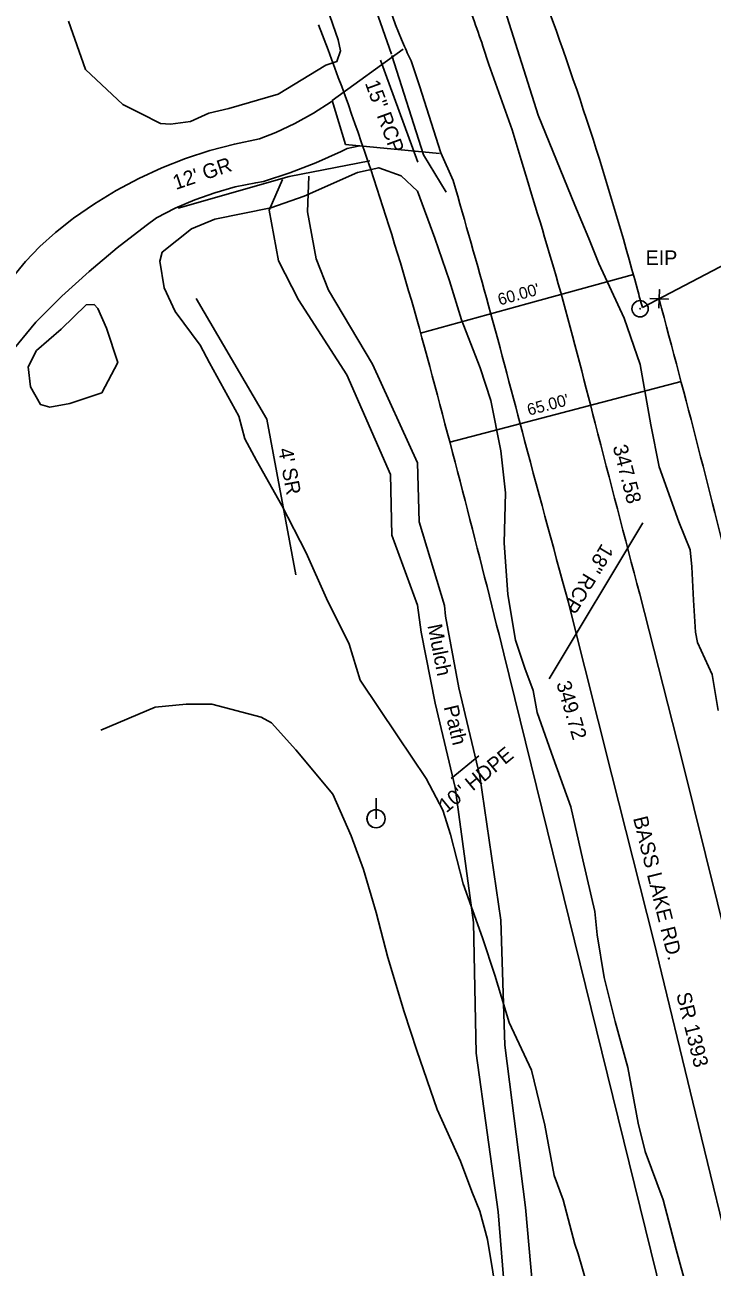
# Model space of a CAD drawing. Extents: x 2057786 to 2059508, y 687766 to 689280.
# Drawn here: x 2058906.4 to 2059093.3, y 688139 to 688476.7 of the extents above; entities that cross this region are included whole.
import ezdxf

# ---------------------------------------------------------------- set-up
doc = ezdxf.new("R2010")
doc.units = 0
for name, color, linetype in [('Exist Other Culture Fence Line', 7, 'Continuous'), ('Exist Other Culture Fence Line Text', 7, 'Continuous'), ('Exist Property Corner CELL', 7, 'Continuous'), ('Exist Property Iron Pin CELL', 7, 'Continuous'), ('Exist Property Iron Pin Text', 7, 'Continuous'), ('Exist Property Line', 7, 'Continuous'), ('Exist Right of Way Line', 7, 'Continuous'), ('Exist Right of Way Width CELL', 7, 'Continuous'), ('Exist Roads EOP', 7, 'Continuous'), ('Exist Roads EOP Other', 7, 'Continuous'), ('Exist Roads EOP Other Text', 7, 'Continuous'), ('Exist Roads EOP Text', 7, 'Continuous'), ('Exist Roads Soil', 7, 'Continuous'), ('Exist Roads Soil Text', 7, 'Continuous'), ('Exist Structure Minor Pipes HDPE 10 Inch', 7, 'Continuous'), ('Exist Structure Minor Pipes HDPE 10 Inch Text', 7, 'Continuous'), ('Exist Structure Minor Pipes RCP 15 Inch', 7, 'Continuous'), ('Exist Structure Minor Pipes RCP 15 Inch Text', 7, 'Continuous'), ('Exist Structure Minor Pipes RCP 18 Inch', 7, 'Continuous'), ('Exist Structure Minor Pipes RCP 18 Inch Invert', 7, 'Continuous'), ('Exist Structure Minor Pipes RCP 18 Inch Text', 7, 'Continuous'), ('Exist Utilities Other Pole CELL', 7, 'Continuous'), ('Exist Utilities Power Pole CELL', 7, 'Continuous'), ('Exist Utilities Telephone UG FO', 7, 'Continuous'), ('Old_Level_11', 7, 'Continuous')]:
    doc.layers.add(name, color=color, linetype=linetype)

# ---------------------------------------------------------------- blocks, each defined once
blk = doc.blocks.new('EXIST PROPERTY IRON PIN')
at = {"layer": 'Exist Property Iron Pin CELL'}
for radius in [0.0441, 0.00141]:
    blk.add_circle((0, 0), radius, dxfattribs=at)
blk = doc.blocks.new('EXIST UTILITIES OTHER POLE')
at = {"layer": 'Exist Utilities Other Pole CELL'}
blk.add_circle((0, 0), 0.0493, dxfattribs=at)

msp = doc.modelspace()

# ---------------------------------------------------------------- linework, layer by layer
at = {"layer": 'Exist Other Culture Fence Line'}
msp.add_lwpolyline([(2058980.05, 688327.2), (2058972.2, 688369.55), (2058953, 688402.37)], dxfattribs=at)
at = {"layer": 'Exist Property Corner CELL'}
msp.add_line((2059078.83, 688402.25), (2059078.83, 688402.25), dxfattribs=at)
msp.add_lwpolyline([(2059076.33, 688402.33), (2059081.32, 688402.17), (2059078.83, 688402.25), (2059078.91, 688404.75), (2059078.74, 688399.75)], dxfattribs=at)
at = {"layer": 'Exist Property Line'}
msp.add_line((2059074.29, 688399.87), (2059264.75, 688499.48), dxfattribs=at)
at = {"layer": 'Exist Right of Way Line'}
for p, q in [((2058988.82, 688469.91), (2058986.23, 688476.73)), ((2059115.34, 687986.62), (2059036.61, 688305.74))]:
    msp.add_line(p, q, dxfattribs=at)
for centre, radius, start, end in [((2058184.94, 688164.34), 920, 15.14804, 20.81311), ((2058184.94, 688164.34), 860, 15.14804, 20.81311), ((2055323.62, 687389.72), 3884.32, 15.07359, 15.14804), ((2055323.62, 687389.72), 3889.32, 13.85856, 15.08996), ((2055323.62, 687389.72), 3824.32, 13.85856, 15.14804)]:
    msp.add_arc(centre, radius, start, end, dxfattribs=at)
at = {"layer": 'Exist Right of Way Width CELL'}
for p, q in [((2059071.84, 688408.87), (2059042.87, 688400.88)), ((2059014, 688392.92), (2059042.87, 688400.88)), ((2059084.81, 688379.79), (2059050.7, 688370.81)), ((2059021.95, 688363.24), (2059050.7, 688370.81))]:
    msp.add_line(p, q, dxfattribs=at)
at = {"layer": 'Exist Roads EOP'}
for p, q in [((2059030.96, 688470.96), (2059032.51, 688465.96)), ((2059011.64, 688466.39), (2059013.7, 688460.15)), ((2059038.87, 688448.22), (2059041.31, 688440.05)), ((2059038.87, 688448.22), (2059041.31, 688440.05)), ((2059019.53, 688441.91), (2059022.86, 688434.4))]:
    msp.add_line(p, q, dxfattribs=at)
for points in [[(2059032.51, 688465.96), (2059038.87, 688448.22)], [(2059013.7, 688460.15), (2059019.53, 688441.91)], [(2059073.57, 688321.95), (2059085.03, 688277.15), (2059107.56, 688186.18), (2059115.88, 688151.54)], [(2059073.57, 688321.95), (2059085.03, 688277.15), (2059107.56, 688186.18), (2059115.88, 688151.54)], [(2059054.97, 688316.74), (2059065.96, 688272.73), (2059077.39, 688227.65), (2059088.71, 688180.92), (2059100.28, 688133.61), (2059110.45, 688090.8), (2059121.23, 688047.29), (2059135.07, 687991.8)]]:
    msp.add_lwpolyline(points, dxfattribs=at)
for points in [[(2058872.96, 688726), (2058891.35, 688704.77), (2058913.31, 688678.93), (2058935.04, 688651.14), (2058956.54, 688621.23), (2058978.08, 688586.33), (2058996.92, 688551.62), (2059015.6, 688510.42), (2059028.28, 688478.53), (2059030.96, 688470.96)], [(2058856.61, 688711.74), (2058876.02, 688692.6), (2058897.43, 688666.21), (2058918.59, 688638.94), (2058939.86, 688608.88), (2058960.51, 688575.45), (2058980.73, 688540.94), (2058998, 688503.14), (2059009.64, 688470.81), (2059011.64, 688466.39)], [(2059041.31, 688440.05), (2059051.42, 688406.33), (2059061.48, 688368.41), (2059073.57, 688321.95)], [(2059041.31, 688440.05), (2059051.42, 688406.33), (2059061.48, 688368.41), (2059073.57, 688321.95)], [(2059022.86, 688434.4), (2059032.48, 688400.41), (2059042.29, 688363.69), (2059054.97, 688316.74)]]:
    msp.add_spline(points, degree=3, dxfattribs=at)
at = {"layer": 'Exist Roads EOP Other'}
for points in [[(2059019.15, 688441.77), (2058993.6, 688444.24), (2058989.91, 688456.13), (2059009.28, 688470.13)], [(2058989.95, 688456.01), (2058989.71, 688455.83), (2058984.87, 688452.7), (2058979.82, 688449.91), (2058974.59, 688447.46), (2058970.17, 688445.73), (2058963.38, 688444.33), (2058956.68, 688442.54), (2058950.09, 688440.37), (2058943.64, 688437.83), (2058937.34, 688434.93), (2058931.21, 688431.67), (2058925.28, 688428.07), (2058919.57, 688424.14), (2058919.12, 688423.82), (2058914.68, 688420.29), (2058910.49, 688416.46), (2058906.58, 688412.35), (2058902.96, 688407.97), (2058899.66, 688403.36), (2058896.68, 688398.53), (2058894.53, 688394.47), (2058887.28, 688384.8)], [(2058902.58, 688370.19), (2058901.55, 688374.69), (2058901.03, 688382.83), (2058902.17, 688387.22), (2058909.37, 688395.93), (2058916.48, 688402.94), (2058923.86, 688409.65), (2058931.5, 688416.07), (2058939.39, 688422.19), (2058942.19, 688424.23), (2058947.3, 688426.88), (2058952.58, 688429.17), (2058958.01, 688431.1), (2058963.55, 688432.65), (2058969.19, 688433.81), (2058971.26, 688434.14), (2058978.45, 688436.49), (2058985.51, 688439.21), (2058992.42, 688442.3), (2058994.05, 688443.1), (2058997.51, 688443.86)]]:
    msp.add_lwpolyline(points, dxfattribs=at)
at = {"layer": 'Exist Roads Soil'}
for p, q in [((2059013.12, 688318.99), (2059014.15, 688311.59)), ((2059020.45, 688318.87), (2059020.75, 688315.96))]:
    msp.add_line(p, q, dxfattribs=at)
for points in [[(2059000.18, 688439.77), (2058978.3, 688435.46), (2058948.08, 688426.85)], [(2059013.12, 688318.99), (2059006.2, 688337.96), (2059005.85, 688354.46), (2058993.92, 688381.57), (2058980.83, 688401.96), (2058975.34, 688412.6), (2058972.81, 688426.38), (2058976.46, 688434.65)], [(2059020.45, 688318.87), (2059013.58, 688341.64), (2059013.12, 688357.65), (2059000.93, 688384.48), (2058988.94, 688404.61), (2058985.61, 688413.09), (2058983.26, 688425.93), (2058983.61, 688435.55)], [(2059064.55, 687998.99), (2059049.49, 688014.71), (2059038.82, 688019.47), (2059031.46, 688025.88), (2059031.46, 688043.27), (2059034.19, 688073.93), (2059035.51, 688085.99), (2059043.26, 688097.2), (2059046.35, 688112.61), (2059042.48, 688155.19), (2059036.86, 688199.32), (2059035.85, 688233.32), (2059030.09, 688272.47), (2059024.35, 688296.5), (2059020.75, 688315.96)], [(2059052.19, 687995.23), (2059048.6, 688004.7), (2059036.59, 688011.96), (2059024.27, 688021.35), (2059024.5, 688046.46), (2059027.79, 688073.73), (2059027.66, 688086.52), (2059036.78, 688100.09), (2059038.39, 688113.89), (2059035.1, 688154.03), (2059029.11, 688197.17), (2059028.34, 688232.68), (2059023.41, 688269.39), (2059017.95, 688292.36), (2059014.15, 688311.59)]]:
    msp.add_lwpolyline(points, dxfattribs=at)
at = {"layer": 'Exist Structure Minor Pipes HDPE 10 Inch'}
msp.add_lwpolyline([(2059022.29, 688271.85), (2059029.83, 688278.06)], dxfattribs=at)
at = {"layer": 'Exist Structure Minor Pipes RCP 15 Inch'}
msp.add_lwpolyline([(2059003.13, 688467.11), (2059013.27, 688439.4)], dxfattribs=at)
at = {"layer": 'Exist Structure Minor Pipes RCP 18 Inch'}
msp.add_lwpolyline([(2059048.99, 688298.95), (2059074.46, 688341.38)], dxfattribs=at)
at = {"layer": 'Exist Utilities Power Pole CELL'}
for q in [(2059001.88, 688266.55), (2059001.88, 688260.92)]:
    msp.add_line((2059001.88, 688260.92), q, dxfattribs=at)
msp.add_circle((2059001.88, 688260.92), 2.45, dxfattribs=at)
at = {"layer": 'Exist Utilities Telephone UG FO'}
for points in [[(2058857, 688692.64), (2058865.87, 688691.02), (2058876.46, 688684.47), (2058890.13, 688671.13), (2058918.75, 688634.8), (2058946.42, 688594.09), (2058970.23, 688552.87), (2058992.38, 688507.83), (2059006.09, 688468.73)], [(2059020.97, 688431.2), (2059014.74, 688441.38), (2059006.21, 688468.36)]]:
    msp.add_lwpolyline(points, dxfattribs=at)
at = {"layer": 'Old_Level_11'}
for points in [[(2058988.55, 688481.24), (2058991.56, 688472.68), (2058992.19, 688469.67), (2058991.23, 688466.74), (2058988.2, 688465.72), (2058975.27, 688457.9), (2058961.87, 688453.97), (2058956.44, 688452.69), (2058951.46, 688450.48), (2058945.96, 688449.69), (2058943.3, 688449.94), (2058937.9, 688452.61), (2058933.07, 688455.06), (2058922.89, 688464.56), (2058918.27, 688477.74)], [(2059087.73, 688329.36), (2059087.31, 688334.01), (2059084.2, 688341.66), (2059078.85, 688356.59), (2059076.64, 688368.03), (2059073.71, 688384.42), (2059069.39, 688396.95), (2059062.46, 688411.86), (2059059.78, 688418.61), (2059055.96, 688427.74), (2059045.97, 688452.14), (2059036.98, 688480.53)], [(2059061.38, 688126.93), (2059056.83, 688142.64), (2059055.92, 688145.3), (2059052.73, 688157.33), (2059050.29, 688163.95), (2059047.75, 688177.64), (2059044.12, 688192.56), (2059038.08, 688205.55), (2059034.14, 688218.42), (2059030.82, 688228.53), (2059025.6, 688243.21), (2059022.08, 688256.66), (2059020.01, 688263.29), (2059015.52, 688271.82), (2059007.7, 688283.48), (2058997.53, 688298.57), (2058994.57, 688308.33), (2058988.43, 688320.79), (2058982.88, 688333.24), (2058976.25, 688346.03), (2058969.41, 688358.3), (2058966.22, 688364.18), (2058964.53, 688370.33), (2058956.59, 688384.86), (2058954.02, 688389.67), (2058947.25, 688398.76), (2058944.26, 688405.28), (2058943.08, 688412.45), (2058943.71, 688414.89), (2058951.69, 688421.29), (2058958.07, 688423.88), (2058973.28, 688427.02), (2058982.29, 688430.12), (2058996.8, 688436.62), (2059002.61, 688437.88), (2059008.7, 688435.64), (2059013.11, 688431.51), (2059017.83, 688418.7), (2059021.83, 688407.12), (2059025.09, 688396.55), (2059030.17, 688383.52), (2059033.12, 688374.58), (2059035.82, 688360.94), (2059037.05, 688349.52), (2059036.68, 688335.94), (2059037.67, 688321.91), (2059039.8, 688309.48), (2059042.32, 688301.89), (2059044.61, 688295.74), (2059045.65, 688289.81), (2059050.06, 688277.43), (2059054.88, 688264.11), (2059058.09, 688249.76), (2059061.39, 688235.67), (2059062.02, 688229.39), (2059063.91, 688217.78), (2059066.86, 688205.82), (2059070.35, 688193.26), (2059073.13, 688178.19), (2059075.04, 688170.49), (2059079.95, 688157.34), (2059083.47, 688143.86), (2059086.37, 688133.2)], [(2058927.31, 688376.69), (2058918.61, 688373.76), (2058913.15, 688372.81), (2058910.63, 688373.55), (2058907.95, 688378.33), (2058907.31, 688383.8), (2058909.59, 688388.2), (2058916.27, 688394.02), (2058923.08, 688400.65), (2058925.19, 688400.69), (2058926.21, 688399.66), (2058928.57, 688394.27), (2058931.69, 688384.91), (2058927.31, 688376.69)], [(2059094.94, 688290.3), (2059093.25, 688300.11), (2059089.33, 688308.85), (2059088.7, 688311.62), (2059088.21, 688320.31), (2059087.73, 688329.36)], [(2058927, 688285), (2058941.8, 688291.21), (2058950.24, 688292.1), (2058957.25, 688292.08), (2058970.67, 688288.54), (2058973.49, 688286.99), (2058980.08, 688279.63), (2058990.11, 688267.6), (2058995.12, 688256.23), (2058998.49, 688247.08), (2059001.91, 688235.41), (2059005.11, 688223.19), (2059009.51, 688208.39), (2059013, 688197.93), (2059018.49, 688181.92), (2059024.87, 688167.84), (2059027.89, 688159.55), (2059030.11, 688154.2), (2059032.2, 688146.54), (2059035.09, 688128.97)]]:
    msp.add_lwpolyline(points, dxfattribs=at)

# ---------------------------------------------------------------- block references
at = {"layer": 'Exist Property Iron Pin CELL', "xscale": 50, "yscale": 50}
msp.add_blockref('EXIST PROPERTY IRON PIN', (2059073.67, 688399.55), dxfattribs=at)
at = {"layer": 'Exist Utilities Other Pole CELL', "xscale": 50, "yscale": 50}
msp.add_blockref('EXIST UTILITIES OTHER POLE', (2059001.88, 688260.92), dxfattribs=at)

# ---------------------------------------------------------------- texts
at = {"layer": 'Exist Other Culture Fence Line Text'}
msp.add_text("4' SR", height=4, rotation=280.4974, dxfattribs=at).set_placement((2058975.26, 688361.36))
at = {"layer": 'Exist Property Iron Pin Text'}
msp.add_text('EIP', height=4, rotation=0, dxfattribs=at).set_placement((2059075.17, 688411.41))
at = {"layer": 'Exist Right of Way Width CELL'}
for s, rotation, p in [("60.00'", 15.4142, (2059035.49, 688400.43)), ("65.00'", 14.7475, (2059043.44, 688370.47))]:
    msp.add_text(s, height=3.2, rotation=rotation, dxfattribs=at).set_placement(p)
at = {"layer": 'Exist Roads EOP Other Text'}
msp.add_text("12' GR", height=4, rotation=18.5934, dxfattribs=at).set_placement((2058947.42, 688431.83))
at = {"layer": 'Exist Roads EOP Text'}
for s, p in [('BASS LAKE RD.', (2059071.74, 688261.08)), ('SR 1393', (2059083.48, 688213.22))]:
    msp.add_text(s, height=4, rotation=283.906, dxfattribs=at).set_placement(p)
at = {"layer": 'Exist Roads Soil Text'}
for s, rotation, p in [('Mulch', 281.1672, (2059015.83, 688313.45)), ('Path', 283.3631, (2059020.26, 688291.31))]:
    msp.add_text(s, height=4, rotation=rotation, dxfattribs=at).set_placement(p)
at = {"layer": 'Exist Structure Minor Pipes HDPE 10 Inch Text'}
msp.add_text('10" HDPE', height=4, rotation=39.4812, dxfattribs=at).set_placement((2059020.96, 688262.34))
at = {"layer": 'Exist Structure Minor Pipes RCP 15 Inch Text'}
msp.add_text('15" RCP', height=4, rotation=290.1022, dxfattribs=at).set_placement((2058998.81, 688460.89))
at = {"layer": 'Exist Structure Minor Pipes RCP 18 Inch Invert'}
for s, rotation, p in [('347.58', 284.3885, (2059066.2, 688362.07)), ('349.72', 286.4006, (2059050.84, 688297.73))]:
    msp.add_text(s, height=4, rotation=rotation, dxfattribs=at).set_placement(p)
at = {"layer": 'Exist Structure Minor Pipes RCP 18 Inch Text'}
msp.add_text('18" RCP', height=4, rotation=239.0194, dxfattribs=at).set_placement((2059063.29, 688335.97))

doc.saveas('drawing.dxf')
